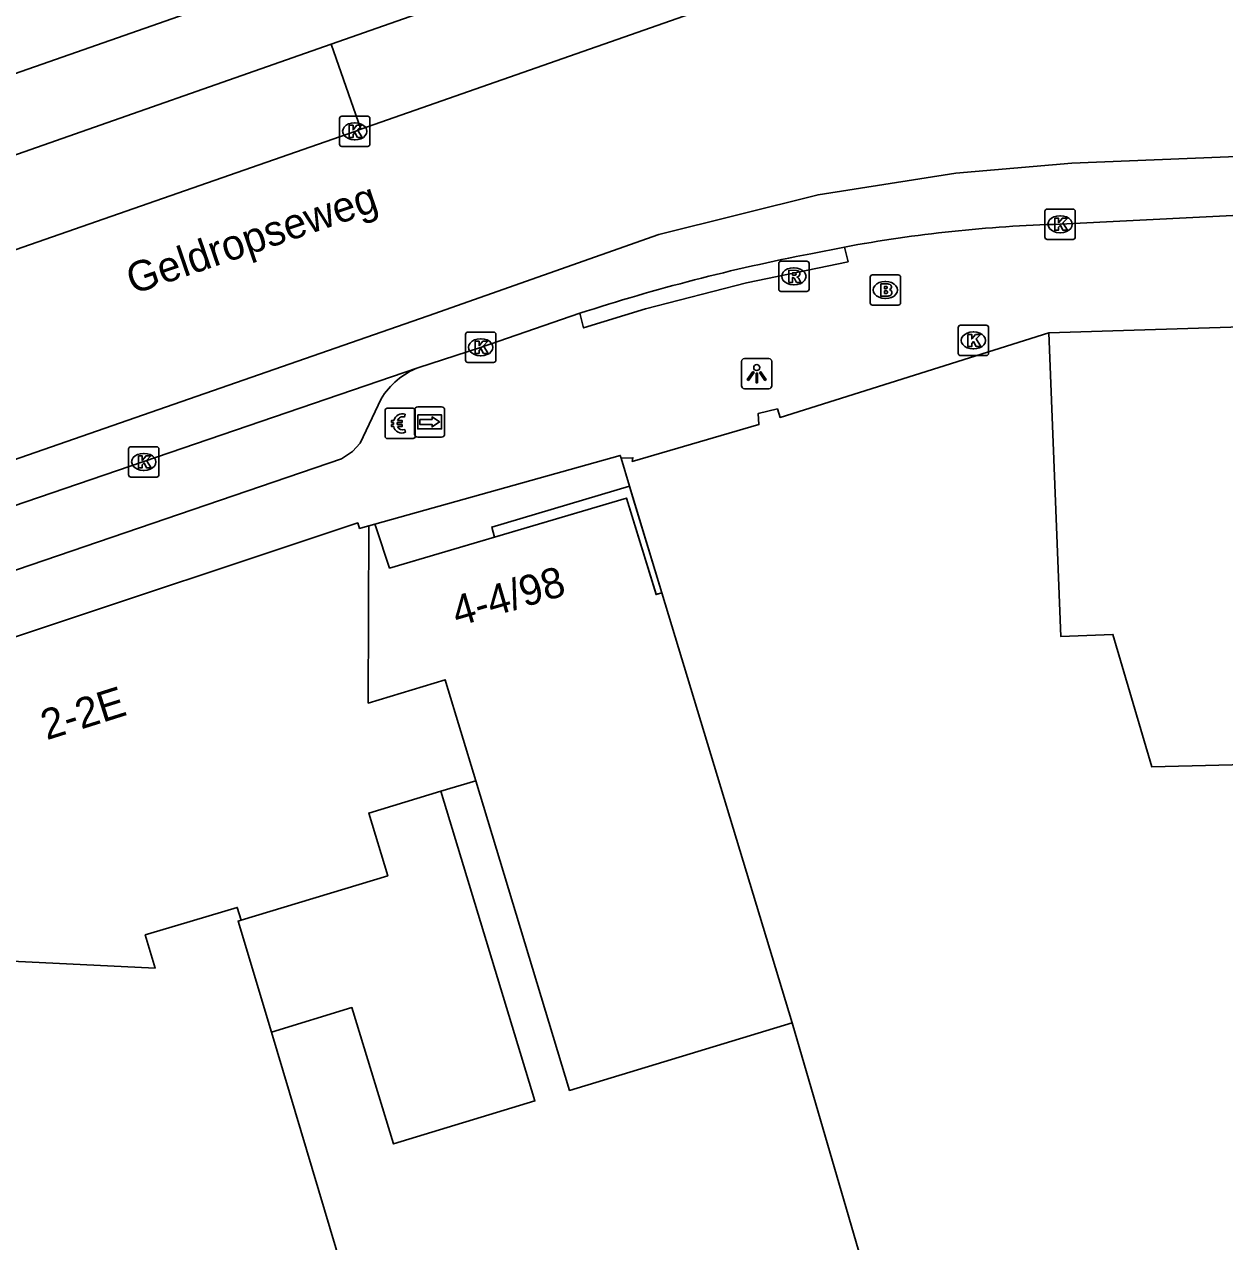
# Model space of a CAD drawing. Extents: x 161087 to 161922, y 382574 to 383873.
# Drawn here: x 161753.78 to 161793.38, y 382798.99 to 382839.17 of the extents above; entities that cross this region are included whole.
import ezdxf

# ---------------------------------------------------------------- set-up
doc = ezdxf.new("R2010")
doc.units = 0
for name, color, linetype in [('IMGEO_Betaalautomaat', 7, 'Continuous'), ('IMGEO_Brandkraan', 7, 'Continuous'), ('IMGEO_Fietspad_gesloten', 7, 'Continuous'), ('IMGEO_Fietspad_open', 7, 'Continuous'), ('IMGEO_Kolk', 7, 'Continuous'), ('IMGEO_Lichtpunt', 7, 'Continuous'), ('IMGEO_Muur', 7, 'Continuous'), ('IMGEO_Openbare_ruimte_label', 7, 'Continuous'), ('IMGEO_Pand', 7, 'Continuous'), ('IMGEO_Pand_nummerreeks', 7, 'Continuous'), ('IMGEO_Pand_overbouw', 7, 'Continuous'), ('IMGEO_Rijbaan_lokaal_gesloten', 7, 'Continuous'), ('IMGEO_Rioolput', 7, 'Continuous'), ('IMGEO_Voetpad_open', 7, 'Continuous'), ('IMGEO_Wegwijzer', 7, 'Continuous')]:
    doc.layers.add(name, color=color, linetype=linetype)

msp = doc.modelspace()

# ---------------------------------------------------------------- linework, layer by layer
at = {"layer": 'IMGEO_Betaalautomaat'}
for p, q in [((161765.681, 382825.571), (161765.681, 382826.412)), ((161765.681, 382826.412), (161765.681, 382825.571)), ((161765.756, 382826.495), (161766.597, 382826.495)), ((161766.597, 382826.495), (161765.756, 382826.495)), ((161766.68, 382826.421), (161766.68, 382825.58)), ((161766.68, 382825.58), (161766.68, 382826.421)), ((161765.964, 382825.959), (161765.964, 382826.027)), ((161766.085, 382826.027), (161766.085, 382825.959)), ((161766.343, 382826.3), (161766.326, 382826.2)), ((161766.33, 382825.794), (161766.352, 382825.707)), ((161766.606, 382825.496), (161765.765, 382825.496)), ((161765.765, 382825.496), (161766.606, 382825.496))]:
    msp.add_line(p, q, dxfattribs=at)
for points in [[(161765.964, 382826.027), (161765.895, 382826.027), (161765.895, 382826.096), (161765.974, 382826.096)], [(161766.096, 382826.096), (161766.243, 382826.096), (161766.243, 382826.027), (161766.085, 382826.027)], [(161765.969, 382825.89), (161765.895, 382825.89), (161765.895, 382825.959), (161765.964, 382825.959)], [(161766.085, 382825.959), (161766.243, 382825.959), (161766.243, 382825.89), (161766.099, 382825.89)]]:
    msp.add_lwpolyline(points, dxfattribs=at)
for centre, radius, start, end in [((161765.759, 382826.418), 0.0779, 92.4484, 184.2845), ((161765.759, 382826.418), 0.0779, 92.4484, 184.2845), ((161766.603, 382826.418), 0.0779, 2.4484, 94.2845), ((161766.603, 382826.418), 0.0779, 2.4484, 94.2845), ((161766.257, 382826.02), 0.293, 73.014, 165.0139), ((161766.263, 382826.033), 0.179, 69.3236, 159.5683), ((161766.23, 382825.945), 0.267, 191.8096, 297.0389), ((161766.263, 382825.96), 0.179, 202.7625, 291.8693), ((161766.603, 382825.574), 0.0779, 272.4484, 4.2845), ((161766.603, 382825.574), 0.0779, 272.4484, 4.2845), ((161765.759, 382825.574), 0.0779, 182.4484, 274.2845), ((161765.759, 382825.574), 0.0779, 182.4484, 274.2845)]:
    msp.add_arc(centre, radius, start, end, dxfattribs=at)
at = {"layer": 'IMGEO_Brandkraan'}
for p, q in [((161781.688, 382829.974), (161781.688, 382830.826)), ((161781.763, 382830.9), (161782.615, 382830.9)), ((161782.689, 382830.826), (161782.689, 382829.974)), ((161782.176, 382830.68), (161782.201, 382830.68)), ((161782.199, 382830.12), (161782.174, 382830.12)), ((161782.615, 382829.9), (161781.763, 382829.9))]:
    msp.add_line(p, q, dxfattribs=at)
for points in [[(161781.688, 382829.974), (161781.688, 382830.826)], [(161781.763, 382830.9), (161782.615, 382830.9)], [(161782.689, 382830.826), (161782.689, 382829.974)], [(161782.036, 382830.6), (161782.036, 382830.2), (161782.249, 382830.2)], [(161782.267, 382830.6), (161782.036, 382830.6)], [(161782.215, 382830.519), (161782.161, 382830.519), (161782.161, 382830.443)], [(161782.161, 382830.443), (161782.214, 382830.443)], [(161782.223, 382830.367), (161782.161, 382830.367), (161782.161, 382830.286)], [(161782.161, 382830.286), (161782.223, 382830.286)], [(161782.615, 382829.9), (161781.763, 382829.9)]]:
    msp.add_lwpolyline(points, dxfattribs=at)
for centre, radius, start, end in [((161781.765, 382830.824), 0.0765, 91.552, 178.448), ((161781.765, 382830.824), 0.0765, 91.552, 178.448), ((161782.613, 382830.824), 0.0765, 1.552, 88.448), ((161782.613, 382830.824), 0.0765, 1.552, 88.448), ((161782.216, 382830.481), 0.0379, 267.8285, 90.9355), ((161782.271, 382830.455), 0.145, 59.4692, 91.5367), ((161782.296, 382830.502), 0.0922, 285.5137, 58.1501), ((161782.301, 382830.31), 0.105, 301.3115, 78.989), ((161782.224, 382830.326), 0.0404, 269.8759, 90.5077), ((161782.255, 382830.451), 0.251, 268.6676, 293.5347), ((161781.765, 382829.976), 0.0765, 181.552, 268.448), ((161781.765, 382829.976), 0.0765, 181.552, 268.448), ((161782.613, 382829.976), 0.0765, 271.552, 358.448), ((161782.613, 382829.976), 0.0765, 271.552, 358.448)]:
    msp.add_arc(centre, radius, start, end, dxfattribs=at)
for centre, major_axis, ratio, start_param, end_param in [((161782.175, 382830.4), (-0.387, 0.002), 0.722429, 4.712389, 7.853982), ((161782.2, 382830.4), (-0.39, 0.002), 0.717154, 1.570796, 4.712389)]:
    msp.add_ellipse(centre, major_axis=major_axis, ratio=ratio, start_param=start_param, end_param=end_param, dxfattribs=at)
at = {"layer": 'IMGEO_Fietspad_gesloten'}
for points in [[(161741.681, 382833.418), (161770.191, 382843.404)], [(161770.624, 382840.877), (161763.899, 382838.518)], [(161763.899, 382838.518), (161743.191, 382831.256), (161742.093, 382830.806)]]:
    msp.add_lwpolyline(points, dxfattribs=at)
at = {"layer": 'IMGEO_Fietspad_open'}
msp.add_lwpolyline([(161764.885, 382835.707), (161763.899, 382838.518)], dxfattribs=at)
at = {"layer": 'IMGEO_Kolk'}
for p, q in [((161764.182, 382835.21), (161764.182, 382836.062)), ((161764.257, 382836.136), (161765.109, 382836.136)), ((161765.183, 382836.062), (161765.183, 382835.21)), ((161764.67, 382835.916), (161764.695, 382835.916)), ((161764.693, 382835.356), (161764.668, 382835.356)), ((161765.109, 382835.136), (161764.257, 382835.136)), ((161787.455, 382832.145), (161787.455, 382832.997)), ((161787.53, 382833.071), (161788.382, 382833.071)), ((161787.943, 382832.851), (161787.968, 382832.851)), ((161788.456, 382832.997), (161788.456, 382832.145)), ((161788.382, 382832.071), (161787.53, 382832.071)), ((161787.966, 382832.291), (161787.941, 382832.291)), ((161784.668, 382829.234), (161785.52, 382829.234)), ((161768.338, 382828.082), (161768.338, 382828.934)), ((161768.413, 382829.008), (161769.265, 382829.008)), ((161768.826, 382828.788), (161768.851, 382828.788)), ((161769.339, 382828.934), (161769.339, 382828.082)), ((161784.593, 382828.308), (161784.593, 382829.16)), ((161785.081, 382829.014), (161785.106, 382829.014)), ((161785.594, 382829.16), (161785.594, 382828.308)), ((161785.104, 382828.454), (161785.079, 382828.454)), ((161769.265, 382828.008), (161768.413, 382828.008)), ((161768.849, 382828.228), (161768.824, 382828.228)), ((161785.52, 382828.234), (161784.668, 382828.234)), ((161757.296, 382825.226), (161758.148, 382825.226)), ((161757.221, 382824.3), (161757.221, 382825.152)), ((161757.709, 382825.006), (161757.734, 382825.006)), ((161758.222, 382825.152), (161758.222, 382824.3)), ((161757.732, 382824.446), (161757.707, 382824.446)), ((161758.148, 382824.226), (161757.296, 382824.226))]:
    msp.add_line(p, q, dxfattribs=at)
for points in [[(161764.182, 382835.21), (161764.182, 382836.062)], [(161764.257, 382836.136), (161765.109, 382836.136)], [(161765.183, 382836.062), (161765.183, 382835.21)], [(161764.503, 382835.836), (161764.626, 382835.836), (161764.626, 382835.685), (161764.756, 382835.836), (161764.92, 382835.836), (161764.774, 382835.685), (161764.927, 382835.436), (161764.775, 382835.436), (161764.69, 382835.6), (161764.626, 382835.533), (161764.626, 382835.436), (161764.503, 382835.436), (161764.503, 382835.836)], [(161765.109, 382835.136), (161764.257, 382835.136)], [(161787.455, 382832.145), (161787.455, 382832.997)], [(161787.53, 382833.071), (161788.382, 382833.071)], [(161788.456, 382832.997), (161788.456, 382832.145)], [(161787.776, 382832.771), (161787.899, 382832.771), (161787.899, 382832.62), (161788.029, 382832.771), (161788.193, 382832.771), (161788.047, 382832.62), (161788.2, 382832.371), (161788.048, 382832.371), (161787.963, 382832.535), (161787.899, 382832.468), (161787.899, 382832.371), (161787.776, 382832.371), (161787.776, 382832.771)], [(161788.382, 382832.071), (161787.53, 382832.071)], [(161784.668, 382829.234), (161785.52, 382829.234)], [(161768.338, 382828.082), (161768.338, 382828.934)], [(161768.413, 382829.008), (161769.265, 382829.008)], [(161769.339, 382828.934), (161769.339, 382828.082)], [(161784.593, 382828.308), (161784.593, 382829.16)], [(161784.914, 382828.934), (161785.037, 382828.934), (161785.037, 382828.783), (161785.167, 382828.934), (161785.331, 382828.934), (161785.185, 382828.783), (161785.338, 382828.534), (161785.186, 382828.534), (161785.101, 382828.698), (161785.037, 382828.631), (161785.037, 382828.534), (161784.914, 382828.534), (161784.914, 382828.934)], [(161785.594, 382829.16), (161785.594, 382828.308)], [(161768.659, 382828.708), (161768.782, 382828.708), (161768.782, 382828.557), (161768.912, 382828.708), (161769.076, 382828.708), (161768.93, 382828.557), (161769.083, 382828.308), (161768.931, 382828.308), (161768.846, 382828.472), (161768.782, 382828.405), (161768.782, 382828.308), (161768.659, 382828.308), (161768.659, 382828.708)], [(161769.265, 382828.008), (161768.413, 382828.008)], [(161785.52, 382828.234), (161784.668, 382828.234)], [(161757.296, 382825.226), (161758.148, 382825.226)], [(161757.221, 382824.3), (161757.221, 382825.152)], [(161757.542, 382824.926), (161757.665, 382824.926), (161757.665, 382824.775), (161757.795, 382824.926), (161757.959, 382824.926), (161757.813, 382824.775), (161757.966, 382824.526), (161757.814, 382824.526), (161757.729, 382824.69), (161757.665, 382824.623), (161757.665, 382824.526), (161757.542, 382824.526), (161757.542, 382824.926)], [(161758.222, 382825.152), (161758.222, 382824.3)], [(161758.148, 382824.226), (161757.296, 382824.226)]]:
    msp.add_lwpolyline(points, dxfattribs=at)
for centre, start, end in [((161764.259, 382836.06), 91.552, 178.448), ((161764.259, 382836.06), 91.552, 178.448), ((161765.107, 382836.06), 1.552, 88.448), ((161765.107, 382836.06), 1.552, 88.448), ((161764.259, 382835.212), 181.552, 268.448), ((161764.259, 382835.212), 181.552, 268.448), ((161765.107, 382835.212), 271.552, 358.448), ((161765.107, 382835.212), 271.552, 358.448), ((161787.532, 382832.995), 91.552, 178.448), ((161787.532, 382832.995), 91.552, 178.448), ((161788.38, 382832.995), 1.552, 88.448), ((161788.38, 382832.995), 1.552, 88.448), ((161787.532, 382832.147), 181.552, 268.448), ((161787.532, 382832.147), 181.552, 268.448), ((161788.38, 382832.147), 271.552, 358.448), ((161788.38, 382832.147), 271.552, 358.448), ((161784.67, 382829.158), 91.552, 178.448), ((161784.67, 382829.158), 91.552, 178.448), ((161785.518, 382829.158), 1.552, 88.448), ((161785.518, 382829.158), 1.552, 88.448), ((161768.415, 382828.932), 91.552, 178.448), ((161768.415, 382828.932), 91.552, 178.448), ((161769.263, 382828.932), 1.552, 88.448), ((161769.263, 382828.932), 1.552, 88.448), ((161768.415, 382828.084), 181.552, 268.448), ((161768.415, 382828.084), 181.552, 268.448), ((161769.263, 382828.084), 271.552, 358.448), ((161769.263, 382828.084), 271.552, 358.448), ((161784.67, 382828.31), 181.552, 268.448), ((161784.67, 382828.31), 181.552, 268.448), ((161785.518, 382828.31), 271.552, 358.448), ((161785.518, 382828.31), 271.552, 358.448), ((161757.298, 382825.15), 91.552, 178.448), ((161757.298, 382825.15), 91.552, 178.448), ((161758.146, 382825.15), 1.552, 88.448), ((161758.146, 382825.15), 1.552, 88.448), ((161757.298, 382824.302), 181.552, 268.448), ((161757.298, 382824.302), 181.552, 268.448), ((161758.146, 382824.302), 271.552, 358.448), ((161758.146, 382824.302), 271.552, 358.448)]:
    msp.add_arc(centre, 0.0765, start, end, dxfattribs=at)
for centre, major_axis, ratio, start_param, end_param in [((161764.669, 382835.636), (-0.387, 0.002), 0.722429, 4.712389, 7.853982), ((161764.694, 382835.636), (-0.39, 0.002), 0.717154, 1.570796, 4.712389), ((161787.942, 382832.571), (-0.387, 0.002), 0.722429, 4.712389, 7.853982), ((161787.967, 382832.571), (-0.39, 0.002), 0.717154, 1.570796, 4.712389), ((161768.825, 382828.508), (-0.387, 0.002), 0.722429, 4.712389, 7.853982), ((161768.85, 382828.508), (-0.39, 0.002), 0.717154, 1.570796, 4.712389), ((161785.08, 382828.734), (-0.387, 0.002), 0.722429, 4.712389, 7.853982), ((161785.105, 382828.734), (-0.39, 0.002), 0.717154, 1.570796, 4.712389), ((161757.708, 382824.726), (-0.387, 0.002), 0.722429, 4.712389, 7.853982), ((161757.733, 382824.726), (-0.39, 0.002), 0.717154, 1.570796, 4.712389)]:
    msp.add_ellipse(centre, major_axis=major_axis, ratio=ratio, start_param=start_param, end_param=end_param, dxfattribs=at)
at = {"layer": 'IMGEO_Lichtpunt'}
for p, q in [((161777.445, 382828.041), (161777.445, 382827.234)), ((161777.445, 382828.041), (161777.445, 382827.234)), ((161778.347, 382828.136), (161777.539, 382828.136)), ((161778.347, 382828.136), (161777.539, 382828.136)), ((161778.441, 382827.234), (161778.441, 382828.041)), ((161778.441, 382827.234), (161778.441, 382828.041)), ((161777.539, 382827.14), (161778.347, 382827.14)), ((161777.539, 382827.14), (161778.347, 382827.14))]:
    msp.add_line(p, q, dxfattribs=at)
for points in [[(161777.819, 382827.705), (161777.858, 382827.677), (161777.67, 382827.415), (161777.632, 382827.442), (161777.819, 382827.705)], [(161777.921, 382827.657), (161777.968, 382827.657), (161777.968, 382827.335), (161777.921, 382827.335), (161777.921, 382827.657)], [(161778.031, 382827.677), (161778.069, 382827.704), (161778.256, 382827.442), (161778.217, 382827.414), (161778.031, 382827.677)]]:
    msp.add_lwpolyline(points, dxfattribs=at)
msp.add_circle((161777.944, 382827.839), 0.0994, dxfattribs=at)
for centre, start, end in [((161777.539, 382828.041), 90, 180), ((161777.539, 382828.041), 90, 180), ((161778.347, 382828.041), 0, 90), ((161778.347, 382828.041), 0, 90), ((161777.539, 382827.234), 180, 270), ((161777.539, 382827.234), 180, 270), ((161778.347, 382827.234), 270, 0), ((161778.347, 382827.234), 270, 360)]:
    msp.add_arc(centre, 0.0946, start, end, dxfattribs=at)
at = {"layer": 'IMGEO_Muur'}
for points in [[(161769.297, 382822.242), (161769.205, 382822.573), (161773.744, 382823.924)], [(161774.81, 382820.403), (161773.845, 382823.588), (161773.744, 382823.924)]]:
    msp.add_lwpolyline(points, dxfattribs=at)
at = {"layer": 'IMGEO_Pand'}
for points in [[(161787.585, 382828.984), (161790.746, 382829.084), (161800.329, 382829.386), (161800.928, 382829.412), (161800.95, 382828.783)], [(161787.585, 382828.984), (161787.977, 382818.963), (161789.696, 382819.03), (161790.979, 382814.663), (161794.957, 382814.762), (161794.798, 382819.842), (161801.26, 382820.026), (161801.106, 382824.375), (161800.95, 382828.783)], [(161774.81, 382820.403), (161774.63, 382820.361), (161773.652, 382823.531), (161769.297, 382822.242)], [(161765.152, 382822.617), (161764.869, 382822.537), (161764.841, 382822.53), (161764.78, 382822.713), (161741.914, 382815.103)], [(161768.675, 382814.202), (161767.689, 382817.455), (161767.666, 382817.533), (161765.13, 382816.764), (161765.152, 382822.617)], [(161769.297, 382822.242), (161765.834, 382821.218), (161765.388, 382822.546), (161765.346, 382822.671), (161765.152, 382822.617)], [(161768.675, 382814.202), (161771.772, 382803.981), (161779.113, 382806.206), (161774.81, 382820.403)], [(161767.527, 382813.855), (161768.675, 382814.202)], [(161737.9, 382813.764), (161739.444, 382809.112), (161750.203, 382808.397), (161758.096, 382808.012), (161757.768, 382809.112), (161758.841, 382809.432), (161760.805, 382810.018), (161760.931, 382809.597)], [(161760.931, 382809.597), (161760.835, 382809.568), (161761.93, 382805.898), (161764.589, 382806.71), (161765.961, 382802.214), (161770.624, 382803.633), (161767.527, 382813.855)], [(161760.931, 382809.597), (161765.771, 382811.063), (161765.144, 382813.132), (161767.527, 382813.855)]]:
    msp.add_lwpolyline(points, dxfattribs=at)
at = {"layer": 'IMGEO_Pand_overbouw'}
for points in [[(161773.652, 382823.531), (161774.622, 382820.343), (161774.81, 382820.403), (161773.744, 382823.924), (161773.468, 382824.848), (161773.441, 382824.94), (161765.346, 382822.671), (161765.388, 382822.546), (161765.834, 382821.218)], [(161779.113, 382806.206), (161771.772, 382803.981), (161768.675, 382814.202), (161767.527, 382813.855), (161770.624, 382803.633), (161765.961, 382802.214), (161764.589, 382806.71), (161761.93, 382805.898), (161766.586, 382790.298), (161773.62, 382792.444), (161774.146, 382790.723), (161782.85, 382793.379)]]:
    msp.add_lwpolyline(points, close=True, dxfattribs=at)
at = {"layer": 'IMGEO_Rijbaan_lokaal_gesloten'}
for points in [[(161764.885, 382835.707), (161777.336, 382840.072)], [(161737.362, 382819.209), (161767.109, 382829.547), (161774.717, 382832.23), (161779.972, 382833.544), (161784.515, 382834.256), (161788.346, 382834.584), (161795.133, 382834.857), (161826.222, 382836.445), (161841.766, 382837.156), (161855.272, 382837.15)], [(161735.002, 382825.222), (161736.346, 382825.698), (161741.488, 382827.556), (161752.01, 382831.223), (161764.683, 382835.636), (161764.885, 382835.707)], [(161817.761, 382834.014), (161800.222, 382833.189), (161787.956, 382832.571)], [(161780.839, 382831.816), (161779.727, 382831.594)], [(161772.113, 382829.631), (161768.826, 382828.505), (161766.768, 382827.835)], [(161766.768, 382827.835), (161737.856, 382817.95)]]:
    msp.add_lwpolyline(points, dxfattribs=at)
for centre, radius, start, end in [((161789.206, 382786.866), 45.722, 91.5666, 100.5444), ((161791.656, 382769.575), 63.156, 100.88788, 108.02585)]:
    msp.add_arc(centre, radius, start, end, dxfattribs=at)
at = {"layer": 'IMGEO_Rioolput'}
for p, q in [((161778.669, 382830.424), (161778.669, 382831.276)), ((161778.744, 382831.35), (161779.596, 382831.35)), ((161779.67, 382831.276), (161779.67, 382830.424)), ((161779.157, 382831.13), (161779.182, 382831.13)), ((161779.18, 382830.57), (161779.155, 382830.57)), ((161779.596, 382830.35), (161778.744, 382830.35))]:
    msp.add_line(p, q, dxfattribs=at)
for points in [[(161778.669, 382830.424), (161778.669, 382831.276)], [(161778.744, 382831.35), (161779.596, 382831.35)], [(161779.67, 382831.276), (161779.67, 382830.424)], [(161779.258, 382831.048), (161779.006, 382831.05), (161779.006, 382830.65)], [(161779.006, 382830.65), (161779.13, 382830.65), (161779.13, 382830.812), (161779.141, 382830.812)], [(161779.184, 382830.969), (161779.13, 382830.969), (161779.13, 382830.888)], [(161779.13, 382830.888), (161779.182, 382830.888)], [(161779.188, 382830.783), (161779.259, 382830.65), (161779.399, 382830.65), (161779.334, 382830.776)], [(161779.596, 382830.35), (161778.744, 382830.35)]]:
    msp.add_lwpolyline(points, dxfattribs=at)
for centre, radius, start, end in [((161778.746, 382831.274), 0.0765, 91.552, 178.448), ((161778.746, 382831.274), 0.0765, 91.552, 178.448), ((161779.594, 382831.274), 0.0765, 1.552, 88.448), ((161779.594, 382831.274), 0.0765, 1.552, 88.448), ((161779.14, 382830.759), 0.0533, 26.0293, 88.6989), ((161779.166, 382831.077), 0.19, 274.7715, 282.9687), ((161779.19, 382830.873), 0.0964, 77.0061, 93.1865), ((161779.204, 382830.93), 0.0378, 276.6634, 79.6772), ((161779.257, 382830.938), 0.109, 350.3612, 89.416), ((161779.255, 382830.938), 0.112, 277.5842, 350.9817), ((161779.239, 382830.723), 0.108, 29.5134, 73.7905), ((161778.746, 382830.426), 0.0765, 181.552, 268.448), ((161778.746, 382830.426), 0.0765, 181.552, 268.448), ((161779.594, 382830.426), 0.0765, 271.552, 358.448), ((161779.594, 382830.426), 0.0765, 271.552, 358.448)]:
    msp.add_arc(centre, radius, start, end, dxfattribs=at)
for centre, major_axis, ratio, start_param, end_param in [((161779.156, 382830.85), (-0.387, 0.002), 0.722429, 4.712389, 7.853982), ((161779.181, 382830.85), (-0.39, 0.002), 0.717154, 1.570796, 4.712389)]:
    msp.add_ellipse(centre, major_axis=major_axis, ratio=ratio, start_param=start_param, end_param=end_param, dxfattribs=at)
at = {"layer": 'IMGEO_Voetpad_open'}
for points in [[(161780.839, 382831.816), (161780.96, 382831.331), (161777.608, 382830.636), (161774.275, 382829.772), (161772.234, 382829.146), (161772.113, 382829.631)], [(161773.744, 382823.924), (161773.468, 382824.848), (161773.86, 382824.86), (161773.84, 382824.74), (161778.016, 382825.956), (161777.988, 382826.317), (161778.629, 382826.473), (161778.716, 382826.192), (161787.585, 382828.984)], [(161741.169, 382817.001), (161741.503, 382817.057), (161764.249, 382824.83), (161764.605, 382825.073), (161764.858, 382825.343), (161765.556, 382826.811)]]:
    msp.add_lwpolyline(points, dxfattribs=at)
msp.add_arc((161767.72, 382825.479), 2.541, 112.0018, 148.3861, dxfattribs=at)
at = {"layer": 'IMGEO_Wegwijzer'}
for p, q in [((161766.658, 382825.644), (161766.658, 382826.444)), ((161766.658, 382826.444), (161766.658, 382825.644)), ((161766.758, 382826.544), (161767.548, 382826.544)), ((161767.548, 382826.544), (161766.758, 382826.544)), ((161767.648, 382826.444), (161767.648, 382825.644)), ((161767.648, 382825.644), (161767.648, 382826.444)), ((161767.548, 382825.544), (161766.758, 382825.544)), ((161766.758, 382825.544), (161767.548, 382825.544))]:
    msp.add_line(p, q, dxfattribs=at)
for points in [[(161766.759, 382826.276), (161767.547, 382826.276), (161767.547, 382825.812), (161766.759, 382825.812), (161766.759, 382826.276)], [(161766.824, 382826.128), (161766.824, 382826.044), (161766.824, 382825.96), (161767.235, 382825.96), (161767.235, 382825.877), (161767.482, 382826.044), (161767.235, 382826.211), (161767.235, 382826.128), (161766.824, 382826.128)]]:
    msp.add_lwpolyline(points, dxfattribs=at)
for centre, start, end in [((161766.758, 382826.444), 90, 180), ((161766.758, 382826.444), 90, 180), ((161767.548, 382826.444), 0, 90), ((161767.548, 382826.444), 360, 90), ((161766.758, 382825.644), 180, 270), ((161766.758, 382825.644), 180, 270), ((161767.548, 382825.644), 270, 0), ((161767.548, 382825.644), 270, 0)]:
    msp.add_arc(centre, 0.1, start, end, dxfattribs=at)

# ---------------------------------------------------------------- texts
at = {"layer": 'IMGEO_Openbare_ruimte_label'}
msp.add_text('Geldropseweg', height=1, rotation=18.9061, dxfattribs=at).set_placement((161757.361, 382830.245))
at = {"layer": 'IMGEO_Pand_nummerreeks'}
for s, rotation, p in [('4-4/98', 16.2892, (161768.064, 382819.28)), ('2-2E', 17.5039, (161754.517, 382815.533))]:
    msp.add_text(s, height=1, rotation=rotation, dxfattribs=at).set_placement(p)

doc.saveas('drawing.dxf')
